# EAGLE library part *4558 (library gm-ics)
*4558 Op Amp Infamous for its use in tube screamers. This op amp has many manufacturers, hence the leading "*" in the name. The JRC4558 is a widely used example.
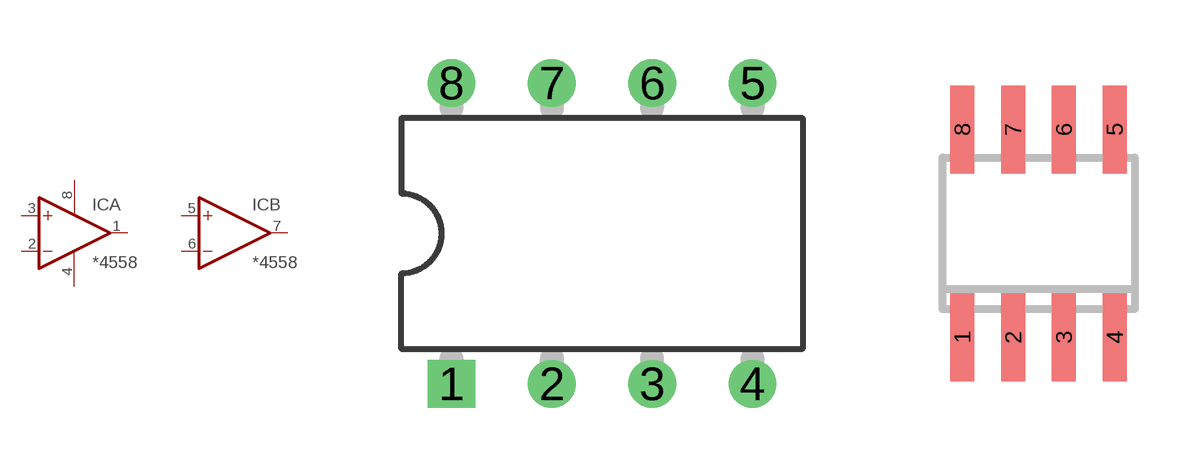
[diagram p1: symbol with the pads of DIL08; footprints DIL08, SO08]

Designator prefix IC; gates A=OPAMP B=OPAMP P=PWR+-

## LM4558N  [DIL08]
1  A:OUT  out
2  A:-IN  in
3  A:+IN  in
4  P:V-  pwr
5  B:+IN  in
6  B:-IN  in
7  B:OUT  out
8  P:V+  pwr

## LM4558D  [SO08]
Pads as for DIL08

## Footprint DIL08 (pad centres in mm)
Dual In Line Package
drill 0.7 square: 1 -3.81,-3.81
drill 0.7 round: 2 -1.27,-3.81; 3 1.27,-3.81; 4 3.81,-3.81; 5 3.81,3.81; 6 1.27,3.81; 7 -1.27,3.81; 8 -3.81,3.81

## Footprint SO08 (pad centres in mm)
Small Outline Package 8 NS Package M08A
smd 0.6 x 2.2: 1 -1.905,-2.6; 2 -0.635,-2.6; 3 0.635,-2.6; 4 1.905,-2.6; 5 1.905,2.6; 6 0.635,2.6; 7 -0.635,2.6; 8 -1.905,2.6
